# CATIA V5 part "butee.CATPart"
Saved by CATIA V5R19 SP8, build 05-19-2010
Part number: butee
Bounding box of the stored display mesh (mm): x -14.5 to 14.5, y -9.942 to 32, z -9.942 to 9.942
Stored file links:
  G:\EU_thinkMotion\CFAO_2010\MMS_groupe3\MMS_groupe3\A reprendre\mmugnier\Systeme_Cric_Y\Systeme_Cric_Y\butee.CATPart
  C:\Users\matthieu\Desktop\CFAO\Systeme_Cric_Y\Cric_Y.CATProduct
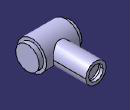
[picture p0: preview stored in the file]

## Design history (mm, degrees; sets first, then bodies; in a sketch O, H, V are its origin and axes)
Set1
  Plane1: linked copy from another document
  Plane2 "Plan inter droit": linked copy from another document
  Plane3 "Plan inter gauche": linked copy from another document
Body1 (main body)
  Sketch1 on Plane1, origin (0, 30, 0), H (-1, 0, 0), V (0, 0, 1)
    circle A1 centre (0, 0) radius 7
    circle A2 centre (0, 0) radius 5
    radius A2 = 5
    radius A1 = 7
  Pad1: profile Sketch1, direction (0, 1, 0), length 2
  Sketch2 on start face of Pad1, origin (0, 30, 0), H (1, 0, 0), V (0, 0, 1)
    projected circle E1 centre (0, 0) radius 7 from edge [start face of Pad1 | face of Pad1 from Sketch1.A1]
    circle A1 centre (0, 0) radius 6
    radius A1 = 6
  Pad2: profile Sketch2, direction (0, -1, 0), length 2
  Sketch3 on end face of Pad2, origin (0, 28, 0), H (1, 0, 0), V (0, 0, 1)
    projected circle E1 centre (0, 0) radius 7 from edge [face of Pad2 | end face of Pad2]
  Pad3: profile Sketch3, direction (0, -1, 0), up to zx-plane
  Sketch4 on xy-plane, origin (0, 0, 0), H (1, 0, 0), V (0, 1, 0)
    line L1 (0, 0) -> (14.5, 0)
    line L2 (14.5, 0) -> (14.5, -8)
    line L3 (14.5, -8) -> (11.5, -8)
    line L4 (11.5, -8) -> (11.5, -10)
    line L5 (11.5, -10) -> (-11.5, -10)
    line L6 (-11.5, -10) -> (-11.5, -8)
    point P6 (-11.5, -8)
    line L7 (-11.5, -8) -> (-14.5, -8)
    line L8 (-14.5, -8) -> (-14.5, 0)
    point P8 (-14.5, 0)
    line L9 (-14.5, 0) -> (0, 0)
    reference intersected line E1 through (-14.5, 0) direction (0, 1) from Plane2
    reference intersected line E2 through (14.5, 0) direction (0, 1) from Plane3
    distance L5 L3 = 2
    length L2 = 8
    distance L2 L4 = 3
    length L7 = 3
    horizontal: L1 H, L3 H, L5 H, L7 H, L9 H
    vertical: L2 V, L4 V, L6 V, L8 V
    coincidence: P6 L3, P8 H, L8 E1, E2 L2
  Shaft1: profile Sketch4, axis Sketch4.L1, angle 360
